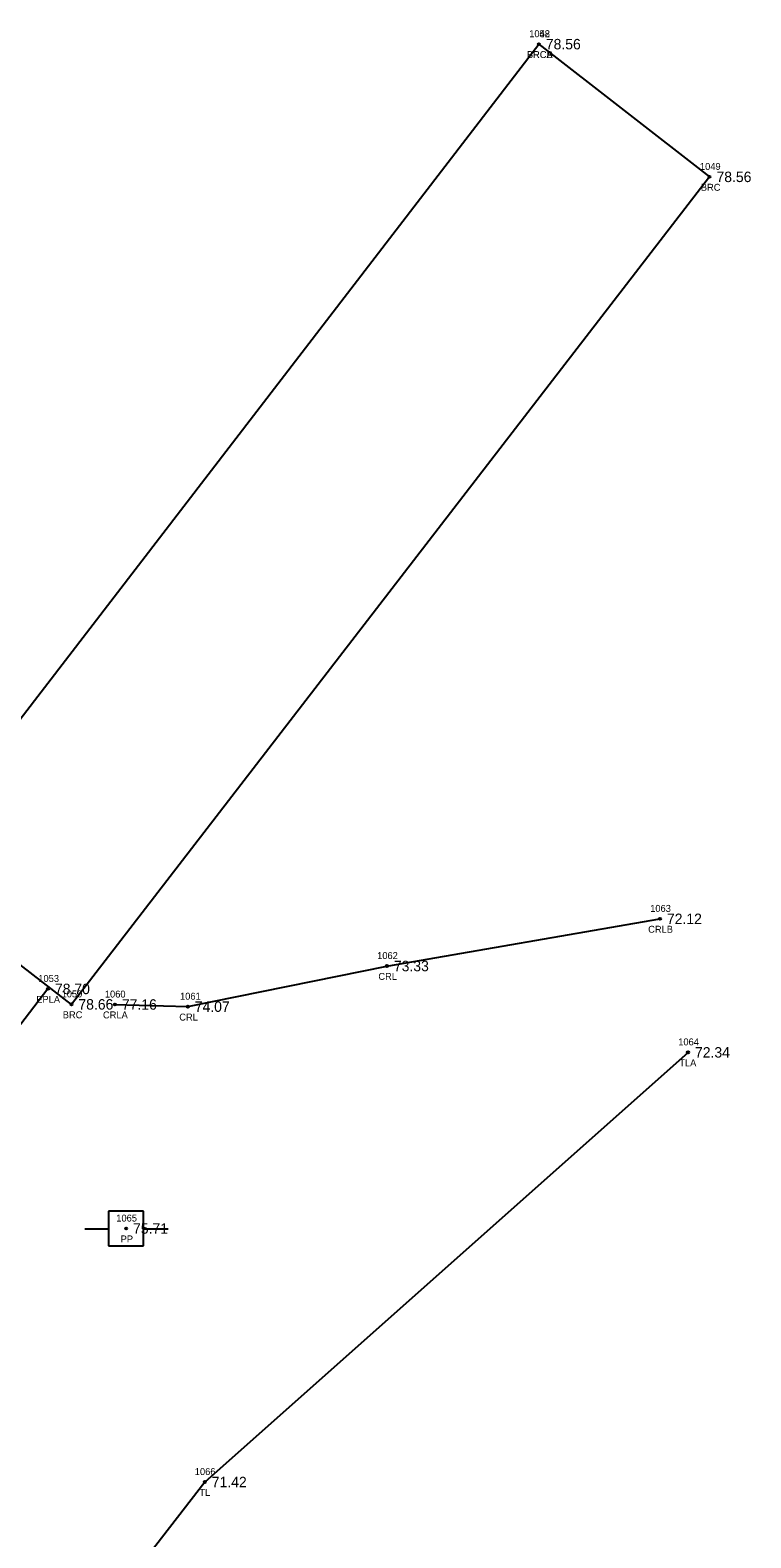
# Model space of a CAD drawing. Extents: x 2505249 to 2506333, y 912937 to 914171.
# Drawn here: x 2506038.1 to 2506141.7, y 913721.3 to 913938 of the extents above; entities that cross this region are included whole.
import ezdxf

# ---------------------------------------------------------------- set-up
doc = ezdxf.new("R2010")
doc.units = 0
for name, color, linetype in [('RD_EX_Bridge', 7, 'Continuous'), ('RD_EX_Bridge_txCode', 7, 'Continuous'), ('RD_EX_H2O', 7, 'Continuous'), ('RD_EX_H2O_txCode', 7, 'Continuous'), ('RD_EX_Road', 7, 'Continuous'), ('RD_EX_Road_txCode', 7, 'Continuous'), ('RD_EX_TX_Bridge_ELEV', 7, 'Continuous'), ('RD_EX_TX_H2O_ELEV', 7, 'Continuous'), ('RD_EX_TX_Road_ELEV', 7, 'Continuous'), ('RD_EX_TX_VEG_ELEV', 7, 'Continuous'), ('RD_EX_UT', 7, 'Continuous'), ('RD_EX_UT_txCode', 7, 'Continuous'), ('RD_EX_VEG', 7, 'Continuous'), ('RD_EX_VEG_txCode', 7, 'Continuous'), ('RD_HC_Survey_ELEV', 7, 'Continuous'), ('RD_SMD_Locator', 7, 'Continuous')]:
    doc.layers.add(name, color=color, linetype=linetype)

msp = doc.modelspace()

# ---------------------------------------------------------------- linework, layer by layer
at = {"layer": 'RD_EX_Bridge'}
msp.add_lwpolyline([(2506111.24, 913935.99), (2506135.76, 913916.92), (2506044.08, 913798.01), (2506019.65, 913816.86), (2506111.24, 913935.99)], dxfattribs=at)
at = {"layer": 'RD_EX_H2O'}
msp.add_lwpolyline([(2506050.33, 913797.99), (2506060.8, 913797.68), (2506089.41, 913803.52), (2506128.64, 913810.3)], dxfattribs=at)
at = {"layer": 'RD_EX_Road'}
msp.add_lwpolyline([(2506040.71, 913800.23), (2505979.73, 913720.47), (2505920.44, 913642.61), (2505859.42, 913562.61), (2505835.44, 913531.43), (2505833.77, 913527.25)], dxfattribs=at)
at = {"layer": 'RD_EX_UT'}
for p, q in [((2506054.42, 913768.31), (2506049.42, 913768.31)), ((2506049.42, 913768.31), (2506049.42, 913763.31)), ((2506054.42, 913763.31), (2506054.42, 913768.31)), ((2506045.99, 913765.75), (2506049.46, 913765.75)), ((2506054.35, 913765.75), (2506057.99, 913765.75)), ((2506049.42, 913763.31), (2506054.42, 913763.31))]:
    msp.add_line(p, q, dxfattribs=at)
at = {"layer": 'RD_EX_VEG'}
msp.add_lwpolyline([(2506132.67, 913791.11), (2506063.24, 913729.37), (2505966.14, 913603.86), (2505918.37, 913544.18)], dxfattribs=at)
at = {"layer": 'RD_SMD_Locator'}
for centre in [(2506111.24, 913935.99), (2506111.24, 913935.99), (2506135.76, 913916.92), (2506128.64, 913810.3), (2506089.41, 913803.52), (2506040.71, 913800.23), (2506044.08, 913798.01), (2506050.33, 913797.99), (2506060.8, 913797.68), (2506132.67, 913791.11), (2506051.93, 913765.8), (2506063.24, 913729.37)]:
    msp.add_circle(centre, 0.15, dxfattribs=at)

# ---------------------------------------------------------------- texts
at = {"layer": 'RD_EX_Bridge_txCode'}
for s, p in [('1048', (2506109.85, 913936.99)), ('1052', (2506109.85, 913936.99)), ('BRCA', (2506109.5, 913933.99)), ('BRCB', (2506109.52, 913933.99)), ('1049', (2506134.38, 913917.92)), ('BRC', (2506134.51, 913914.92)), ('1050', (2506042.66, 913799.01)), ('BRC', (2506042.83, 913796.01))]:
    msp.add_text(s, height=1, dxfattribs=at).set_placement(p)
at = {"layer": 'RD_EX_H2O_txCode'}
for s, p in [('1063', (2506127.23, 913811.3)), ('CRLB', (2506126.94, 913808.3)), ('1062', (2506088, 913804.52)), ('CRL', (2506088.18, 913801.52)), ('1060', (2506048.88, 913798.99)), ('1061', (2506059.68, 913798.68)), ('CRLA', (2506048.61, 913795.99)), ('CRL', (2506059.57, 913795.68))]:
    msp.add_text(s, height=1, dxfattribs=at).set_placement(p)
at = {"layer": 'RD_EX_Road_txCode'}
for s, p in [('1053', (2506039.32, 913801.23)), ('EPLA', (2506039.02, 913798.23))]:
    msp.add_text(s, height=1, dxfattribs=at).set_placement(p)
at = {"layer": 'RD_EX_TX_Bridge_ELEV'}
for s, p in [('78.56', (2506112.24, 913935.24)), ('78.56', (2506112.24, 913935.24)), ('78.56', (2506136.76, 913916.17)), ('78.66', (2506045.08, 913797.26))]:
    msp.add_text(s, height=1.5, dxfattribs=at).set_placement(p)
at = {"layer": 'RD_EX_TX_H2O_ELEV'}
for s, p in [('72.12', (2506129.64, 913809.55)), ('73.33', (2506090.41, 913802.77)), ('77.16', (2506051.33, 913797.24)), ('74.07', (2506061.8, 913796.93))]:
    msp.add_text(s, height=1.5, dxfattribs=at).set_placement(p)
at = {"layer": 'RD_EX_TX_Road_ELEV'}
msp.add_text('78.70', height=1.5, dxfattribs=at).set_placement((2506041.71, 913799.48))
at = {"layer": 'RD_EX_TX_VEG_ELEV'}
for s, p in [('72.34', (2506133.67, 913790.36)), ('71.42', (2506064.24, 913728.62))]:
    msp.add_text(s, height=1.5, dxfattribs=at).set_placement(p)
at = {"layer": 'RD_EX_UT_txCode'}
for s, p in [('1065', (2506050.52, 913766.8)), ('PP', (2506051.15, 913763.8))]:
    msp.add_text(s, height=1, dxfattribs=at).set_placement(p)
at = {"layer": 'RD_EX_VEG_txCode'}
for s, p in [('1064', (2506131.26, 913792.11)), ('TLA', (2506131.41, 913789.11)), ('1066', (2506061.8, 913730.37)), ('TL', (2506062.46, 913727.37))]:
    msp.add_text(s, height=1, dxfattribs=at).set_placement(p)
at = {"layer": 'RD_HC_Survey_ELEV'}
msp.add_text('75.71', height=1.5, dxfattribs=at).set_placement((2506052.93, 913765.05))

doc.saveas('drawing.dxf')
